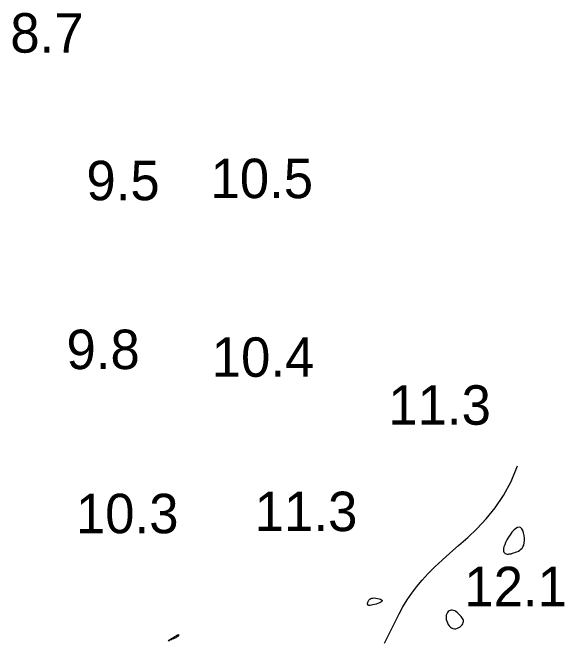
# Model space of a CAD drawing. Extents: x 3040093 to 3056816, y 408076 to 509144.
# Drawn here: x 3044843.3 to 3044913.2, y 435222.9 to 435302.7 of the extents above; entities that cross this region are included whole.
import ezdxf

# ---------------------------------------------------------------- set-up
doc = ezdxf.new("R2010")
doc.units = 0
doc.layers.add('V-CHAN-CONT-EL12-1112', color=7, linetype='Continuous')
doc.layers.add('V-TOPO-SOUN-0810', color=7, linetype='Continuous')

msp = doc.modelspace()

# ---------------------------------------------------------------- linework, layer by layer
at = {"layer": 'V-CHAN-CONT-EL12-1112'}
msp.add_lwpolyline([(3044890.415, 435222.84), (3044890.894, 435223.752), (3044891.353, 435224.682), (3044891.806, 435225.619), (3044892.269, 435226.546), (3044892.759, 435227.451), (3044893.29, 435228.324), (3044893.869, 435229.17), (3044894.503, 435230), (3044895.198, 435230.824), (3044895.962, 435231.652), (3044896.799, 435232.494), (3044897.718, 435233.361), (3044898.723, 435234.263), (3044899.815, 435235.211), (3044900.968, 435236.231), (3044902.147, 435237.348), (3044903.32, 435238.588), (3044904.453, 435239.977), (3044905.513, 435241.542), (3044906.465, 435243.309), (3044907.278, 435245.303)], dxfattribs=at)
for points in [[(3044907.212, 435234.427), (3044907.393, 435234.512), (3044907.564, 435234.613), (3044907.721, 435234.734), (3044907.86, 435234.882), (3044907.978, 435235.062), (3044908.07, 435235.277), (3044908.132, 435235.535), (3044908.161, 435235.834), (3044908.157, 435236.161), (3044908.121, 435236.494), (3044908.054, 435236.814), (3044907.957, 435237.1), (3044907.83, 435237.333), (3044907.675, 435237.492), (3044907.493, 435237.558), (3044907.285, 435237.516), (3044907.059, 435237.379), (3044906.823, 435237.166), (3044906.585, 435236.895), (3044906.354, 435236.584), (3044906.137, 435236.252), (3044905.944, 435235.918), (3044905.782, 435235.6), (3044905.658, 435235.314), (3044905.571, 435235.061), (3044905.52, 435234.841), (3044905.503, 435234.653), (3044905.516, 435234.495), (3044905.558, 435234.367), (3044905.627, 435234.267), (3044905.721, 435234.195), (3044905.837, 435234.15), (3044905.973, 435234.128), (3044906.125, 435234.127), (3044906.29, 435234.146), (3044906.466, 435234.18), (3044906.649, 435234.228), (3044906.837, 435234.286), (3044907.025, 435234.353)], [(3044888.292, 435227.768), (3044888.287, 435227.796), (3044888.285, 435227.825), (3044888.284, 435227.857), (3044888.287, 435227.894), (3044888.294, 435227.937), (3044888.306, 435227.988), (3044888.325, 435228.048), (3044888.35, 435228.119), (3044888.385, 435228.195), (3044888.433, 435228.274), (3044888.497, 435228.352), (3044888.579, 435228.423), (3044888.682, 435228.484), (3044888.81, 435228.53), (3044888.964, 435228.558), (3044889.146, 435228.564), (3044889.344, 435228.549), (3044889.545, 435228.517), (3044889.736, 435228.47), (3044889.904, 435228.41), (3044890.034, 435228.341), (3044890.115, 435228.265), (3044890.131, 435228.184), (3044890.075, 435228.101), (3044889.957, 435228.019), (3044889.791, 435227.939), (3044889.593, 435227.863), (3044889.376, 435227.795), (3044889.155, 435227.735), (3044888.945, 435227.686), (3044888.762, 435227.651), (3044888.615, 435227.631), (3044888.504, 435227.623), (3044888.424, 435227.627), (3044888.368, 435227.64), (3044888.333, 435227.66), (3044888.313, 435227.685), (3044888.302, 435227.712), (3044888.297, 435227.741)], [(3044898.251, 435225.825), (3044898.309, 435225.613), (3044898.393, 435225.406), (3044898.501, 435225.209), (3044898.629, 435225.031), (3044898.775, 435224.88), (3044898.936, 435224.763), (3044899.108, 435224.687), (3044899.29, 435224.659), (3044899.475, 435224.673), (3044899.658, 435224.724), (3044899.834, 435224.805), (3044899.996, 435224.91), (3044900.14, 435225.033), (3044900.259, 435225.166), (3044900.348, 435225.304), (3044900.403, 435225.44), (3044900.426, 435225.576), (3044900.418, 435225.709), (3044900.383, 435225.842), (3044900.325, 435225.973), (3044900.245, 435226.104), (3044900.147, 435226.234), (3044900.033, 435226.364), (3044899.907, 435226.493), (3044899.77, 435226.618), (3044899.626, 435226.733), (3044899.477, 435226.835), (3044899.325, 435226.92), (3044899.172, 435226.982), (3044899.022, 435227.017), (3044898.876, 435227.021), (3044898.737, 435226.991), (3044898.608, 435226.928), (3044898.493, 435226.835), (3044898.393, 435226.716), (3044898.314, 435226.573), (3044898.257, 435226.409), (3044898.225, 435226.228), (3044898.223, 435226.032)], [(3044863.014, 435223.156), (3044863.077, 435223.208), (3044863.176, 435223.277), (3044863.3, 435223.359), (3044863.439, 435223.448), (3044863.583, 435223.537), (3044863.721, 435223.62), (3044863.842, 435223.692), (3044863.94, 435223.748), (3044864.014, 435223.79), (3044864.07, 435223.819), (3044864.11, 435223.838), (3044864.137, 435223.851), (3044864.157, 435223.858), (3044864.172, 435223.863), (3044864.186, 435223.869), (3044864.203, 435223.876), (3044864.22, 435223.885), (3044864.239, 435223.895), (3044864.258, 435223.905), (3044864.276, 435223.913), (3044864.293, 435223.919), (3044864.306, 435223.922), (3044864.316, 435223.92), (3044864.322, 435223.914), (3044864.324, 435223.903), (3044864.323, 435223.888), (3044864.319, 435223.87), (3044864.314, 435223.851), (3044864.308, 435223.83), (3044864.301, 435223.809), (3044864.295, 435223.789), (3044864.289, 435223.77), (3044864.28, 435223.75), (3044864.264, 435223.729), (3044864.239, 435223.704), (3044864.199, 435223.674), (3044864.142, 435223.637), (3044864.063, 435223.592), (3044863.959, 435223.537), (3044863.828, 435223.472), (3044863.679, 435223.401), (3044863.522, 435223.328), (3044863.369, 435223.259), (3044863.228, 435223.2), (3044863.113, 435223.155), (3044863.032, 435223.129), (3044862.996, 435223.129)]]:
    msp.add_lwpolyline(points, close=True, dxfattribs=at)

# ---------------------------------------------------------------- texts
at = {"layer": 'V-TOPO-SOUN-0810'}
for s, p in [('8.7', (3044842.992, 435297.67)), ('10.5 ', (3044868.363, 435279.23)), ('9.5', (3044852.635, 435278.97)), ('9.8', (3044850.112, 435257.57)), ('10.4 ', (3044868.523, 435256.59)), ('11.3 ', (3044890.903, 435250.52)), ('11.3 ', (3044873.973, 435237.04)), ('10.3 ', (3044851.303, 435236.77)), ('12.1 ', (3044900.543, 435227.52))]:
    msp.add_text(s, height=5, dxfattribs=at).set_placement(p)

doc.saveas('drawing.dxf')
